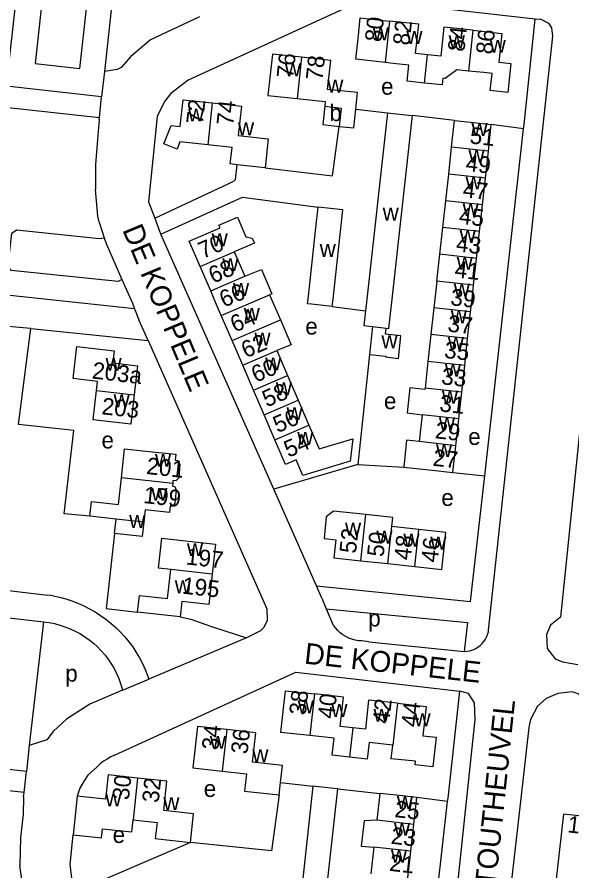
# Model space of a CAD drawing. Extents: x 161936 to 163647, y 386450 to 388633.
# Drawn here: x 162153.8 to 162286.5, y 387613.3 to 387817.5 of the extents above; entities that cross this region are included whole.
import ezdxf

# ---------------------------------------------------------------- set-up
doc = ezdxf.new("R2010")
doc.units = 0
for name, color, linetype in [('BLT_Basislijn', 7, 'Continuous'), ('BLT_Bebouwing', 7, 'Continuous'), ('BLT_Centroide', 7, 'Continuous'), ('BLT_Huisnummer', 7, 'Continuous'), ('BLT_Huisnummer_ tussenligend', 7, 'Continuous'), ('BLT_Huisnummer_reeks', 7, 'Continuous'), ('BLT_Onderverdeling_panden', 7, 'Continuous'), ('BLT_Straatnaam', 7, 'Continuous')]:
    doc.layers.add(name, color=color, linetype=linetype)

msp = doc.modelspace()

# ---------------------------------------------------------------- linework, layer by layer
at = {"layer": 'BLT_Basislijn'}
for p, q in [((162173.46, 387793.42), (162173.99, 387798.45)), ((162234.79, 387795.47), (162242.38, 387794.63)), ((162173.41, 387792.98), (162173.46, 387793.42)), ((162258.4, 387792.76), (162248.36, 387793.96)), ((162173.41, 387792.98), (162173.02, 387788.19)), ((162274.9, 387790.74), (162267.19, 387791.79)), ((162265.65, 387707.74), (162274.9, 387790.74)), ((162173.02, 387788.19), (162172.55, 387782.21)), ((162172.55, 387782.21), (162172.54, 387776.27)), ((162173.52, 387768.18), (162174.62, 387764.7)), ((162215.14, 387704.59), (162188.18, 387765.55)), ((162178.79, 387754.76), (162181.35, 387749.06)), ((162181.86, 387747.72), (162144.36, 387751.74)), ((162181.35, 387749.06), (162181.86, 387747.72)), ((162181.86, 387747.72), (162182.86, 387745.12)), ((162229.15, 387748.25), (162237.1, 387747.26)), ((162185.15, 387740.1), (162182.86, 387745.12)), ((162157.03, 387742.99), (162185.15, 387740.1)), ((162238.03, 387736.8), (162235.28, 387710.48)), ((162235.28, 387710.48), (162215.14, 387704.59)), ((162235.28, 387710.48), (162246.23, 387709.88)), ((162258, 387708.58), (162265.65, 387707.74)), ((162225.41, 387681.46), (162215.14, 387704.59)), ((162226.64, 387678.52), (162225.41, 387681.46)), ((162162.4, 387679.05), (162161.12, 387679.21)), ((162226.64, 387678.52), (162227.73, 387675.92)), ((162227.73, 387675.92), (162229.12, 387672.61)), ((162227.73, 387675.92), (162261.51, 387672.7)), ((162261.51, 387672.7), (162260.72, 387665.76)), ((162266.42, 387670.82), (162266.4, 387670.29)), ((162208.62, 387669.03), (162185.3, 387659.16)), ((162237.88, 387668.1), (162236.26, 387668.29)), ((162237.88, 387668.1), (162260.72, 387665.76)), ((162178.99, 387656.48), (162185.3, 387659.16)), ((162155.45, 387632), (162155.99, 387637.01)), ((162216.8, 387634.45), (162224.52, 387633.56)), ((162155.34, 387630.95), (162155.45, 387632)), ((162230.47, 387632.88), (162240.54, 387631.78)), ((162155.34, 387630.95), (162155.19, 387626.78)), ((162247.29, 387546.76), (162256.74, 387629.85)), ((162256.74, 387629.85), (162249.39, 387630.8)), ((162155.19, 387626.78), (162154.57, 387621.3)), ((162154.57, 387621.3), (162154.43, 387614.55)), ((162195.26, 387620.09), (162167.95, 387608.39)), ((162155.31, 387608.34), (162154.43, 387614.55))]:
    msp.add_line(p, q, dxfattribs=at)
for points in [[(162173.46, 387793.42), (162145.03, 387796.5), (162144.11, 387797.49), (162147.05, 387823.63), (162147.16, 387824.69), (162153.83, 387823.94)], [(162277.67, 387817.03), (162236.65, 387821.68), (162194.65, 387802.43), (162190.57, 387799.23), (162189.04, 387797.32), (162187.24, 387793.74), (162185.17, 387773.27), (162186.7, 387769.43)], [(162197.42, 387817.55), (162185.65, 387812.09), (162181, 387808.08), (162178.67, 387805.4), (162177.72, 387804.96), (162174.66, 387804.5)], [(162277.67, 387817.03), (162278.86, 387817.07), (162280.84, 387816.05), (162281.57, 387814.93), (162281.84, 387812.97), (162266.42, 387670.82)], [(162274.9, 387790.74), (162275.01, 387791.77), (162277.67, 387817.03)], [(162303.81, 387812.76), (162301.05, 387812.14), (162299.21, 387810.71), (162297.42, 387807.01), (162283.73, 387673.93), (162281.38, 387672.06), (162280.36, 387669.83), (162280.52, 387666.46), (162282.43, 387664.01), (162284.21, 387663.3), (162287.89, 387662.65)], [(162213.07, 387781.47), (162229.22, 387779.49), (162230.8, 387791.36)], [(162186.7, 387769.43), (162205.62, 387778.26), (162206.02, 387778.62), (162206.41, 387782.19)], [(162173.52, 387768.18), (162173.06, 387769.88), (162172.54, 387776.27)], [(162188.18, 387765.55), (162207.68, 387774.42), (162225.78, 387772.04)], [(162186.7, 387769.43), (162187.84, 387766.32), (162188.18, 387765.55)], [(162178.79, 387754.76), (162177.95, 387754.22), (162152.37, 387756.87), (162151.66, 387757.96), (162152.55, 387765.79), (162153.65, 387766.6), (162173.5, 387764.54), (162174.62, 387764.7)], [(162174.62, 387764.7), (162175.06, 387763.3), (162178.79, 387754.76)], [(162157.03, 387742.99), (162147.96, 387743.78)], [(162167.34, 387718.61), (162154.1, 387720.07), (162157.03, 387742.99)], [(162185.15, 387740.1), (162213.5, 387675.95), (162213.61, 387673.18), (162212.77, 387671.46), (162211.98, 387670.73), (162208.62, 387669.03)], [(162171.15, 387698.09), (162165.03, 387698.69), (162167.34, 387718.61)], [(162110.95, 387712.34), (162108.01, 387685.52), (162161.12, 387679.21)], [(162225.41, 387681.46), (162262.21, 387677.7), (162265.58, 387707.17), (162265.65, 387707.74)], [(162177.1, 387693.94), (162175.07, 387676.07), (162182.58, 387675.16)], [(162162.4, 387679.05), (162163.92, 387678.73), (162165.41, 387678.34), (162166.88, 387677.86), (162168.33, 387677.31), (162169.74, 387676.69), (162171.12, 387675.99), (162172.46, 387675.22), (162173.76, 387674.39), (162175.02, 387673.49), (162176.23, 387672.52), (162177.38, 387671.49), (162178.48, 387670.41), (162179.52, 387669.27), (162180.51, 387668.08), (162181.43, 387666.83), (162182.28, 387665.55), (162183.07, 387664.22), (162183.79, 387662.85), (162184.43, 387661.44), (162185, 387660), (162185.3, 387659.16)], [(162160.1, 387672.82), (162161.41, 387672.65), (162162.7, 387672.41), (162163.97, 387672.08), (162165.22, 387671.68), (162166.45, 387671.21), (162167.64, 387670.65), (162168.8, 387670.03), (162169.92, 387669.34), (162170.99, 387668.58), (162172.02, 387667.76), (162173, 387666.88), (162173.92, 387665.94), (162174.77, 387664.94), (162175.57, 387663.9), (162176.31, 387662.81), (162176.97, 387661.67), (162177.57, 387660.5), (162178.09, 387659.29), (162178.54, 387658.06), (162178.91, 387656.8), (162178.99, 387656.48)], [(162192.78, 387674.05), (162195.31, 387673.49), (162200.02, 387671.8), (162208.62, 387669.03)], [(162236.26, 387668.29), (162235.45, 387668.34), (162234.65, 387668.47), (162233.87, 387668.67), (162233.11, 387668.95), (162232.38, 387669.31), (162231.69, 387669.73), (162231.05, 387670.23), (162230.46, 387670.78), (162229.93, 387671.39), (162229.46, 387672.04), (162229.12, 387672.61)], [(162260.72, 387665.76), (162261.4, 387665.8), (162262.08, 387665.93), (162262.73, 387666.13), (162263.36, 387666.4), (162263.95, 387666.75), (162264.49, 387667.16), (162264.99, 387667.64), (162265.42, 387668.17), (162265.79, 387668.74), (162266.09, 387669.36), (162266.32, 387670), (162266.4, 387670.29)], [(162155.45, 387632), (162126.96, 387635.13), (162126.12, 387636.17), (162129.02, 387662.09), (162129.15, 387663.2), (162135.93, 387662.44)], [(162177.11, 387640.93), (162220.44, 387660.78), (162259.65, 387656.28)], [(162178.99, 387656.48), (162171.16, 387653.15), (162165.61, 387649.59), (162162.44, 387646.62), (162160.86, 387644.62), (162156.7, 387643.23)], [(162254.99, 387570.33), (162263.33, 387649.52), (162263.17, 387653.5), (162261.71, 387655.67), (162259.65, 387656.28)], [(162256.74, 387629.85), (162256.84, 387630.67), (162259.65, 387656.28)], [(162288.74, 387647.53), (162289.3, 387653.46), (162288.8, 387654.68), (162287.93, 387655.64), (162286.51, 387656.08), (162283.06, 387655.74), (162280.33, 387654.52), (162278.21, 387652.67), (162276.54, 387649.46), (162276.18, 387647.57), (162274.26, 387630.6)], [(162177.11, 387640.93), (162176.19, 387640.52), (162175.3, 387640.03), (162174.45, 387639.48), (162173.65, 387638.87), (162172.89, 387638.19), (162170.73, 387636.2), (162169.64, 387634.59), (162168.79, 387633.03), (162168.15, 387631.14)], [(162216.47, 387631.45), (162214.61, 387618.11), (162195.26, 387620.09)], [(162274.26, 387630.6), (162267.18, 387568.37), (162267.46, 387564.12), (162268.25, 387560.3), (162268.81, 387558.75), (162270.26, 387556.38), (162272.41, 387554.17), (162275, 387552.73), (162279.67, 387551.69), (162296, 387550.24)], [(162167.95, 387608.39), (162166.94, 387610.97), (162166.49, 387614.81), (162167.17, 387621.9)]]:
    msp.add_lwpolyline(points, dxfattribs=at)
at = {"layer": 'BLT_Bebouwing'}
for p, q in [((162177.97, 387834.33), (162174.66, 387804.5)), ((162174.66, 387804.5), (162173.99, 387798.45)), ((162257.7, 387786.36), (162258.4, 387792.76)), ((162266.48, 387785.39), (162267.19, 387791.79)), ((162256.99, 387779.96), (162257.7, 387786.36)), ((162265.77, 387778.99), (162266.48, 387785.39)), ((162213.07, 387781.47), (162206.41, 387782.19)), ((162256.28, 387773.56), (162256.99, 387779.96)), ((162265.07, 387772.59), (162265.77, 387778.99)), ((162255.57, 387767.16), (162256.28, 387773.56)), ((162264.36, 387766.19), (162265.07, 387772.59)), ((162254.87, 387760.76), (162255.57, 387767.16)), ((162263.65, 387759.79), (162264.36, 387766.19)), ((162205.69, 387761.36), (162208.22, 387755.49)), ((162254.16, 387754.36), (162254.87, 387760.76)), ((162262.95, 387753.39), (162263.65, 387759.79)), ((162200.07, 387752.03), (162197.56, 387757.86)), ((162214.17, 387751.07), (162216.75, 387745.1)), ((162253.45, 387747.95), (162252.75, 387741.55)), ((162261.53, 387740.58), (162262.24, 387746.98)), ((162205.18, 387740.15), (162202.62, 387746.09)), ((162238.78, 387743.46), (162238.03, 387736.8)), ((162207.74, 387734.21), (162205.18, 387740.15)), ((162252.75, 387741.55), (162252.04, 387735.15)), ((162260.83, 387734.18), (162261.53, 387740.58)), ((162215.88, 387737.72), (162218.44, 387731.78)), ((162210.3, 387728.28), (162207.74, 387734.21)), ((162252.04, 387735.15), (162251.33, 387728.75)), ((162260.12, 387727.78), (162260.83, 387734.18)), ((162218.44, 387731.78), (162220.99, 387725.85)), ((162212.86, 387722.34), (162210.3, 387728.28)), ((162220.99, 387725.85), (162223.55, 387719.91)), ((162259.41, 387721.38), (162260.12, 387727.78)), ((162215.41, 387716.4), (162212.86, 387722.34)), ((162250.62, 387722.35), (162249.92, 387715.95)), ((162258.7, 387714.98), (162259.41, 387721.38)), ((162258, 387708.58), (162258.7, 387714.98)), ((162249.86, 387694.92), (162243.41, 387695.62)), ((162236, 387687.47), (162242.45, 387686.77)), ((162242.45, 387686.77), (162248.9, 387686.07)), ((162137.4, 387675.43), (162160.1, 387672.82)), ((162192.78, 387674.05), (162182.58, 387675.16)), ((162160.1, 387672.82), (162156.7, 387643.23)), ((162156.7, 387643.23), (162155.99, 387637.01)), ((162216.47, 387631.45), (162216.8, 387634.45)), ((162224.52, 387633.56), (162219.3, 387586.07)), ((162240.54, 387631.78), (162239.83, 387625.39)), ((162248.67, 387624.39), (162249.39, 387630.8)), ((162284.47, 387626.84), (162279.71, 387584.47)), ((162247.95, 387617.98), (162248.67, 387624.39)), ((162239.12, 387618.98), (162238.4, 387612.57)), ((162247.23, 387611.58), (162247.95, 387617.98))]:
    msp.add_line(p, q, dxfattribs=at)
for points in [[(162153.83, 387823.94), (162159.96, 387823.26), (162158.09, 387806.37), (162168.75, 387805.18), (162171.39, 387828.97), (162154.6, 387830.84)], [(162173.99, 387798.45), (162151.27, 387800.97), (162153.83, 387823.94)], [(162241.77, 387806.62), (162234.78, 387807.41), (162235.31, 387812.32), (162235.85, 387817.29), (162242.84, 387816.53)], [(162251.96, 387808.49), (162249.07, 387808.8), (162249.83, 387815.77), (162242.84, 387816.53)], [(162262.78, 387814.34), (162255.86, 387815.09), (162255.1, 387808.15), (162251.96, 387808.49)], [(162262.78, 387814.34), (162269.71, 387813.59), (162268.96, 387806.71), (162271.88, 387806.39), (162271.13, 387799.48), (162266.94, 387799.94), (162267.38, 387803.99), (162265.43, 387804.21), (162261.72, 387804.58)], [(162221.83, 387807.91), (162214.85, 387808.66), (162213.77, 387798.77), (162220.76, 387798.02)], [(162234.79, 387795.47), (162235.22, 387799.42), (162228.05, 387800.19), (162228.81, 387807.15), (162221.83, 387807.91)], [(162251.23, 387801.72), (162247.05, 387802.18), (162247.47, 387806), (162243.71, 387806.41), (162241.77, 387806.62)], [(162261.72, 387804.58), (162258.96, 387804.84), (162256.15, 387802.84), (162255.59, 387802.91), (162255.41, 387801.27), (162251.23, 387801.72)], [(162199.37, 387786.96), (162192.73, 387787.69), (162192.06, 387785.94), (162188.89, 387787.15), (162190.59, 387791.59), (162192.79, 387791.35), (162193.48, 387797.71), (162200.46, 387796.95)], [(162220.76, 387798.02), (162224.41, 387797.63), (162227.46, 387797.3), (162227.34, 387796.16)], [(162200.46, 387796.95), (162207.43, 387796.2), (162206.67, 387789.19), (162213.83, 387788.41), (162213.07, 387781.47)], [(162227.34, 387796.16), (162226.86, 387791.79), (162230.8, 387791.36)], [(162230.8, 387791.36), (162234.3, 387790.98), (162234.79, 387795.47)], [(162242.38, 387794.63), (162237.4, 387750), (162237.1, 387747.26)], [(162242.07, 387743.09), (162242.68, 387743.02), (162243.46, 387750), (162248.36, 387793.96)], [(162242.38, 387794.63), (162247.35, 387794.07), (162248.36, 387793.96)], [(162258.4, 387792.76), (162262.22, 387792.34), (162267.19, 387791.79)], [(162206.41, 387782.19), (162204.77, 387782.37), (162205.2, 387786.32), (162199.37, 387786.96)], [(162229.15, 387748.25), (162224.18, 387748.8), (162223.24, 387748.9), (162223.36, 387750), (162225.23, 387767.07), (162225.78, 387772.04)], [(162229.15, 387748.25), (162229.34, 387750), (162231.69, 387771.39), (162225.78, 387772.04)], [(162197.56, 387757.86), (162194.95, 387763.9), (162202.31, 387767.07), (162202.03, 387767.71), (162206.49, 387769.63), (162208.5, 387764.97), (162210.03, 387764.62), (162210.53, 387763.45), (162205.69, 387761.36)], [(162208.22, 387755.49), (162212.21, 387757.13), (162214.72, 387751.31), (162214.17, 387751.07)], [(162254.16, 387754.36), (162253.68, 387750), (162253.45, 387747.95)], [(162262.24, 387746.98), (162262.57, 387750), (162262.95, 387753.39)], [(162202.62, 387746.09), (162200.94, 387750), (162200.07, 387752.03)], [(162237.1, 387747.26), (162236.7, 387743.69), (162238.78, 387743.46)], [(162216.75, 387745.1), (162219.33, 387739.12), (162215.88, 387737.72)], [(162238.03, 387736.8), (162241.94, 387736.37), (162241.92, 387736.21), (162244.98, 387735.86), (162245.58, 387741.25), (162241.91, 387741.66), (162242.07, 387743.09)], [(162172.74, 387728.16), (162172.99, 387730.35), (162167.18, 387731.02), (162168.07, 387738.68), (162177.02, 387737.65), (162176.68, 387734.77), (162182.59, 387734.09), (162181.78, 387727.11)], [(162181.78, 387727.11), (162180.97, 387720.13), (162171.93, 387721.18), (162172.74, 387728.16)], [(162251.33, 387728.75), (162251.29, 387728.4), (162247.71, 387728.8), (162247.05, 387722.82), (162250.62, 387722.35)], [(162223.55, 387719.91), (162226.01, 387714.2), (162234.05, 387716.63), (162233.46, 387711.27), (162222.11, 387707.88), (162220.52, 387711.56), (162217.97, 387710.46), (162215.41, 387716.4)], [(162249.92, 387715.95), (162246.93, 387716.28), (162246.23, 387709.88)], [(162178.71, 387707.27), (162179.46, 387714.25), (162186.77, 387713.46), (162191.74, 387712.92), (162191.59, 387711.54), (162192.23, 387711.46), (162192.71, 387710.54), (162192.45, 387707.31), (162191.73, 387706.55), (162191.06, 387706.62), (162190.99, 387705.94)], [(162246.23, 387709.88), (162253.03, 387709.13), (162258, 387708.58)], [(162171.15, 387698.09), (162171.53, 387701.59), (162178.02, 387700.89), (162178.71, 387707.27)], [(162190.99, 387705.94), (162190.91, 387705.27), (162191.53, 387705.2), (162191.82, 387704.4), (162191.48, 387701.21), (162191.02, 387700.48), (162190.4, 387700.55), (162190.23, 387698.97), (162184.37, 387699.6), (162184.06, 387696.7)], [(162237.2, 387698.51), (162229.45, 387699.35), (162227.73, 387697.95), (162227.21, 387692.75), (162230.02, 387692.45), (162229.56, 387688.17), (162236, 387687.47)], [(162177.47, 387697.4), (162171.15, 387698.09)], [(162177.1, 387693.94), (162177.47, 387697.4)], [(162243.41, 387695.62), (162243.66, 387697.8), (162237.2, 387698.51)], [(162184.06, 387696.7), (162183.68, 387693.23), (162177.1, 387693.94)], [(162248.9, 387686.07), (162255.34, 387685.36), (162256.3, 387694.22), (162249.86, 387694.92)], [(162190.52, 387685.33), (162187.59, 387685.69), (162188.37, 387692.86), (162196.22, 387692), (162201.19, 387691.46), (162200.4, 387684.24)], [(162182.58, 387675.16), (162183.01, 387679.13), (162189.76, 387678.4), (162190.52, 387685.33)], [(162200.4, 387684.24), (162199.61, 387677.03), (162193.19, 387677.74), (162192.78, 387674.05)], [(162155.99, 387637.01), (162133.31, 387639.61), (162135.93, 387662.44)], [(162223.79, 387645.64), (162216.85, 387646.41), (162217.4, 387651.4), (162217.95, 387656.37), (162224.89, 387655.6)], [(162234.07, 387647.47), (162231.06, 387647.81), (162231.84, 387654.83), (162224.89, 387655.6)], [(162244.74, 387653.37), (162237.85, 387654.14), (162237.08, 387647.14), (162234.07, 387647.47)], [(162244.74, 387653.37), (162251.62, 387652.61), (162250.84, 387645.58), (162253.98, 387645.23), (162253.2, 387638.2), (162249.01, 387638.66), (162249.09, 387639.5), (162243.27, 387640.09), (162243.63, 387643.38)], [(162203.9, 387647.07), (162196.93, 387647.84), (162195.82, 387637.89), (162202.8, 387637.12)], [(162216.8, 387634.45), (162217.25, 387638.5), (162210.1, 387639.3), (162210.88, 387646.29), (162203.9, 387647.07)], [(162233.29, 387640.47), (162229.13, 387640.93), (162229.58, 387644.99), (162223.79, 387645.64)], [(162243.63, 387643.38), (162237.96, 387644.01), (162237.52, 387640), (162233.29, 387640.47)], [(162182.59, 387635.48), (162175.58, 387636.23), (162174.95, 387630.42), (162168.15, 387631.14)], [(162202.8, 387637.12), (162208.64, 387636.47), (162208.18, 387632.37), (162216.47, 387631.45)], [(162195.26, 387620.09), (162195.99, 387626.96), (162188.86, 387627.72), (162189.61, 387634.74), (162182.59, 387635.48)], [(162221.09, 387582.45), (162223.9, 387582.14), (162224.86, 387582.03), (162230.47, 387632.88)], [(162230.47, 387632.88), (162229.49, 387632.99), (162224.52, 387633.56)], [(162168.15, 387631.14), (162167.17, 387621.9)], [(162249.39, 387630.8), (162244.42, 387631.35), (162240.54, 387631.78)], [(162301.26, 387624.05), (162301.36, 387624.98), (162284.47, 387626.84)], [(162167.17, 387621.9), (162173.97, 387621.17), (162174.2, 387623.36), (162181.22, 387622.61), (162181.52, 387625.49)], [(162181.52, 387625.49), (162187.24, 387624.88), (162186.83, 387620.99), (162195.26, 387620.09)], [(162239.83, 387625.39), (162236.76, 387625.24), (162236.08, 387619.21), (162239.12, 387618.98)]]:
    msp.add_lwpolyline(points, dxfattribs=at)
at = {"layer": 'BLT_Onderverdeling_panden'}
for p, q in [((162242.84, 387816.53), (162241.77, 387806.62)), ((162262.78, 387814.34), (162261.72, 387804.58)), ((162221.83, 387807.91), (162220.76, 387798.02)), ((162251.23, 387801.72), (162251.96, 387808.49)), ((162200.46, 387796.95), (162199.37, 387786.96)), ((162266.48, 387785.39), (162257.7, 387786.36)), ((162265.77, 387778.99), (162256.99, 387779.96)), ((162265.07, 387772.59), (162256.28, 387773.56)), ((162264.36, 387766.19), (162255.57, 387767.16)), ((162197.56, 387757.86), (162205.69, 387761.36)), ((162263.65, 387759.79), (162254.87, 387760.76)), ((162200.07, 387752.03), (162208.22, 387755.49)), ((162262.95, 387753.39), (162254.16, 387754.36)), ((162202.62, 387746.09), (162214.17, 387751.07)), ((162262.24, 387746.98), (162253.45, 387747.95)), ((162205.18, 387740.15), (162216.75, 387745.1)), ((162238.78, 387743.46), (162242.07, 387743.09)), ((162261.53, 387740.58), (162252.75, 387741.55)), ((162207.74, 387734.21), (162215.88, 387737.72)), ((162260.83, 387734.18), (162252.04, 387735.15)), ((162210.3, 387728.28), (162218.44, 387731.78)), ((162172.74, 387728.16), (162181.78, 387727.11)), ((162260.12, 387727.78), (162251.33, 387728.75)), ((162212.86, 387722.34), (162220.99, 387725.85)), ((162259.41, 387721.38), (162250.62, 387722.35)), ((162215.41, 387716.4), (162223.55, 387719.91)), ((162258.7, 387714.98), (162249.92, 387715.95)), ((162190.99, 387705.94), (162178.71, 387707.27)), ((162184.06, 387696.7), (162177.47, 387697.4)), ((162236, 387687.47), (162237.2, 387698.51)), ((162242.45, 387686.77), (162243.41, 387695.62)), ((162248.9, 387686.07), (162249.86, 387694.92)), ((162200.4, 387684.24), (162190.52, 387685.33)), ((162224.89, 387655.6), (162223.79, 387645.64)), ((162244.74, 387653.37), (162243.63, 387643.38)), ((162203.9, 387647.07), (162202.8, 387637.12)), ((162234.07, 387647.47), (162233.29, 387640.47)), ((162182.59, 387635.48), (162181.52, 387625.49)), ((162248.67, 387624.39), (162239.83, 387625.39)), ((162247.95, 387617.98), (162239.12, 387618.98))]:
    msp.add_line(p, q, dxfattribs=at)
msp.add_lwpolyline([(162227.34, 387796.16), (162231.29, 387795.73), (162230.8, 387791.36)], dxfattribs=at)

# ---------------------------------------------------------------- texts
at = {"layer": 'BLT_Centroide'}
for s, p in [('w', (162238.81, 387811.97)), ('w', (162246.86, 387811.08)), ('w', (162257, 387810.02)), ('w', (162266.8, 387808.98)), ('w', (162217.8, 387803.34)), ('w', (162227.94, 387799.44)), ('e', (162240.83, 387798.93)), ('w', (162194.67, 387792.53)), ('b', (162228.46, 387792.61)), ('w', (162206.59, 387789.22)), ('w', (162262.45, 387789.06)), ('w', (162261.73, 387782.69)), ('w', (162261.02, 387776.28)), ('w', (162260.32, 387769.88)), ('w', (162241.2, 387768.83)), ('w', (162200.3, 387762.69)), ('w', (162259.62, 387763.47)), ('w', (162226.14, 387760.14)), ('w', (162202.86, 387756.75)), ('w', (162258.91, 387757.06)), ('w', (162205.41, 387750.81)), ('w', (162258.2, 387750.66)), ('w', (162207.98, 387744.88)), ('w', (162257.49, 387744.28)), ('e', (162222.71, 387741.56)), ('w', (162210.53, 387738.94)), ('w', (162240.91, 387738.29)), ('w', (162256.79, 387737.88)), ('w', (162213.09, 387733)), ('w', (162174.93, 387732.91)), ('w', (162256.08, 387731.47)), ('w', (162215.65, 387727.06)), ('w', (162255.37, 387725.06)), ('w', (162176.86, 387724.16)), ('e', (162241.51, 387723.71)), ('w', (162218.2, 387721.12)), ('w', (162254.66, 387718.66)), ('w', (162220.77, 387715.19)), ('e', (162261.67, 387715.16)), ('e', (162173.96, 387714.32)), ('w', (162253.96, 387712.25)), ('w', (162186.76, 387709.94)), ('w', (162185.88, 387701.81)), ('e', (162255.24, 387700.57)), ('w', (162180.58, 387695.31)), ('w', (162232.2, 387693.47)), ('w', (162239.7, 387691.55)), ('w', (162246.16, 387690.84)), ('w', (162252.59, 387690.14)), ('w', (162194.39, 387688.56)), ('w', (162191.48, 387679.7)), ('p', (162237.75, 387671.73)), ('p', (162165.29, 387658.54)), ('w', (162220.88, 387651)), ('w', (162228.92, 387650.11)), ('w', (162239.02, 387648.95)), ('w', (162248.8, 387647.86)), ('w', (162199.86, 387642.48)), ('w', (162210.03, 387639.27)), ('e', (162198.42, 387630.96)), ('w', (162174.88, 387628.69)), ('w', (162188.75, 387627.8)), ('w', (162244.61, 387628.09)), ('w', (162243.9, 387621.69)), ('e', (162176.63, 387619.95)), ('w', (162243.18, 387615.28))]:
    msp.add_text(s, height=4, dxfattribs=at).set_placement(p)
at = {"layer": 'BLT_Huisnummer'}
for s, rotation, p in [('80', 83.7997, (162240.9, 387811.41)), ('86', 83.796, (162267.45, 387808.45)), ('76', 83.7955, (162219.8, 387802.75)), ('78', 83.7955, (162226.78, 387802.21)), ('72', 83.7989, (162198.19, 387791.71)), ('74', 83.7989, (162205.43, 387791.43)), ('51', 353.6948, (162261.89, 387787.28)), ('47', 353.6999, (162260.23, 387774.41)), ('70', 23.3073, (162198.17, 387759.62)), ('43', 353.6927, (162258.63, 387761.45)), ('66', 23.3098, (162203.24, 387747.96)), ('39', 353.6977, (162257.28, 387748.59)), ('62', 23.3039, (162208.46, 387735.85)), ('35', 353.6963, (162255.8, 387735.99)), ('203a', 353.3806, (162171.58, 387731.07)), ('58', 23.3064, (162213.48, 387724.11)), ('203', 353.8327, (162173.87, 387722.51)), ('31', 353.6956, (162254.66, 387723.21)), ('54', 23.3099, (162218.67, 387712.07)), ('27', 353.6952, (162253.06, 387710.2)), ('201', 353.8327, (162184.57, 387708.23)), ('199', 353.8327, (162183.86, 387701.27)), ('52', 83.7991, (162234.81, 387689.08)), ('46', 83.7991, (162254.34, 387686.91)), ('197', 353.7567, (162194.03, 387686.59)), ('195', 353.7567, (162193.09, 387679.61)), ('38', 83.6562, (162222.79, 387650.38)), ('44', 83.658, (162249.57, 387647.54)), ('34', 83.6535, (162201.89, 387642.05)), ('36', 83.6535, (162208.86, 387641.09)), ('30', 83.9003, (162180.51, 387630.11)), ('32', 83.9003, (162187.62, 387629.44)), ('25', 353.5937, (162243.92, 387626.17)), ('21', 353.5957, (162242.66, 387613.31))]:
    msp.add_text(s, height=4, rotation=rotation, dxfattribs=at).set_placement(p)
at = {"layer": 'BLT_Huisnummer_ tussenligend'}
for s, rotation, p in [('82', 83.7997, (162247.6, 387810.6)), ('84', 83.7997, (162260.73, 387809.09)), ('49', 353.6999, (162260.92, 387780.7)), ('45', 353.6927, (162259.32, 387768.09)), ('68', 23.3098, (162200.65, 387753.7)), ('41', 353.6977, (162258.28, 387755.24)), ('64', 23.3039, (162205.84, 387742)), ('37', 353.6963, (162256.61, 387742.28)), ('60', 23.3064, (162210.87, 387729.99)), ('33', 353.6956, (162255.1, 387729.69)), ('56', 23.3099, (162216.07, 387717.95)), ('29', 353.6952, (162253.61, 387716.77)), ('50', 83.7991, (162241.41, 387688.26)), ('48', 83.7991, (162247.88, 387687.46)), ('40', 83.6562, (162229.62, 387649.55)), ('42', 83.6562, (162242.76, 387648.33)), ('23', 353.5957, (162243.03, 387619.79))]:
    msp.add_text(s, height=4, rotation=rotation, dxfattribs=at).set_placement(p)
at = {"layer": 'BLT_Huisnummer_reeks'}
msp.add_text('14', height=4, rotation=353.4854, dxfattribs=at).set_placement((162285.26, 387622.52))
at = {"layer": 'BLT_Straatnaam'}
for s, height, rotation, p in [('DE KOPPELE', 5, 292.6583, (162178.88, 387766.63)), ('DE KOPPELE', 5, 353.7206, (162222.31, 387662.88)), ('DE STOUTHEUVEL', 4.9999, 84.0333, (162266.6, 387593.79))]:
    msp.add_text(s, height=height, rotation=rotation, dxfattribs=at).set_placement(p)

doc.saveas('drawing.dxf')
